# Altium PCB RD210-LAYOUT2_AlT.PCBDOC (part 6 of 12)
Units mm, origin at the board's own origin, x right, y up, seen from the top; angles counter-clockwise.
Board outline 250 x 123 mm, 4 copper layers (TOP, Mid-Layer 1, Mid-Layer 2, BOTTOM), stack 0.711 mm thick; 1043 components, 659 nets, 2786 pads, 1228 vias.
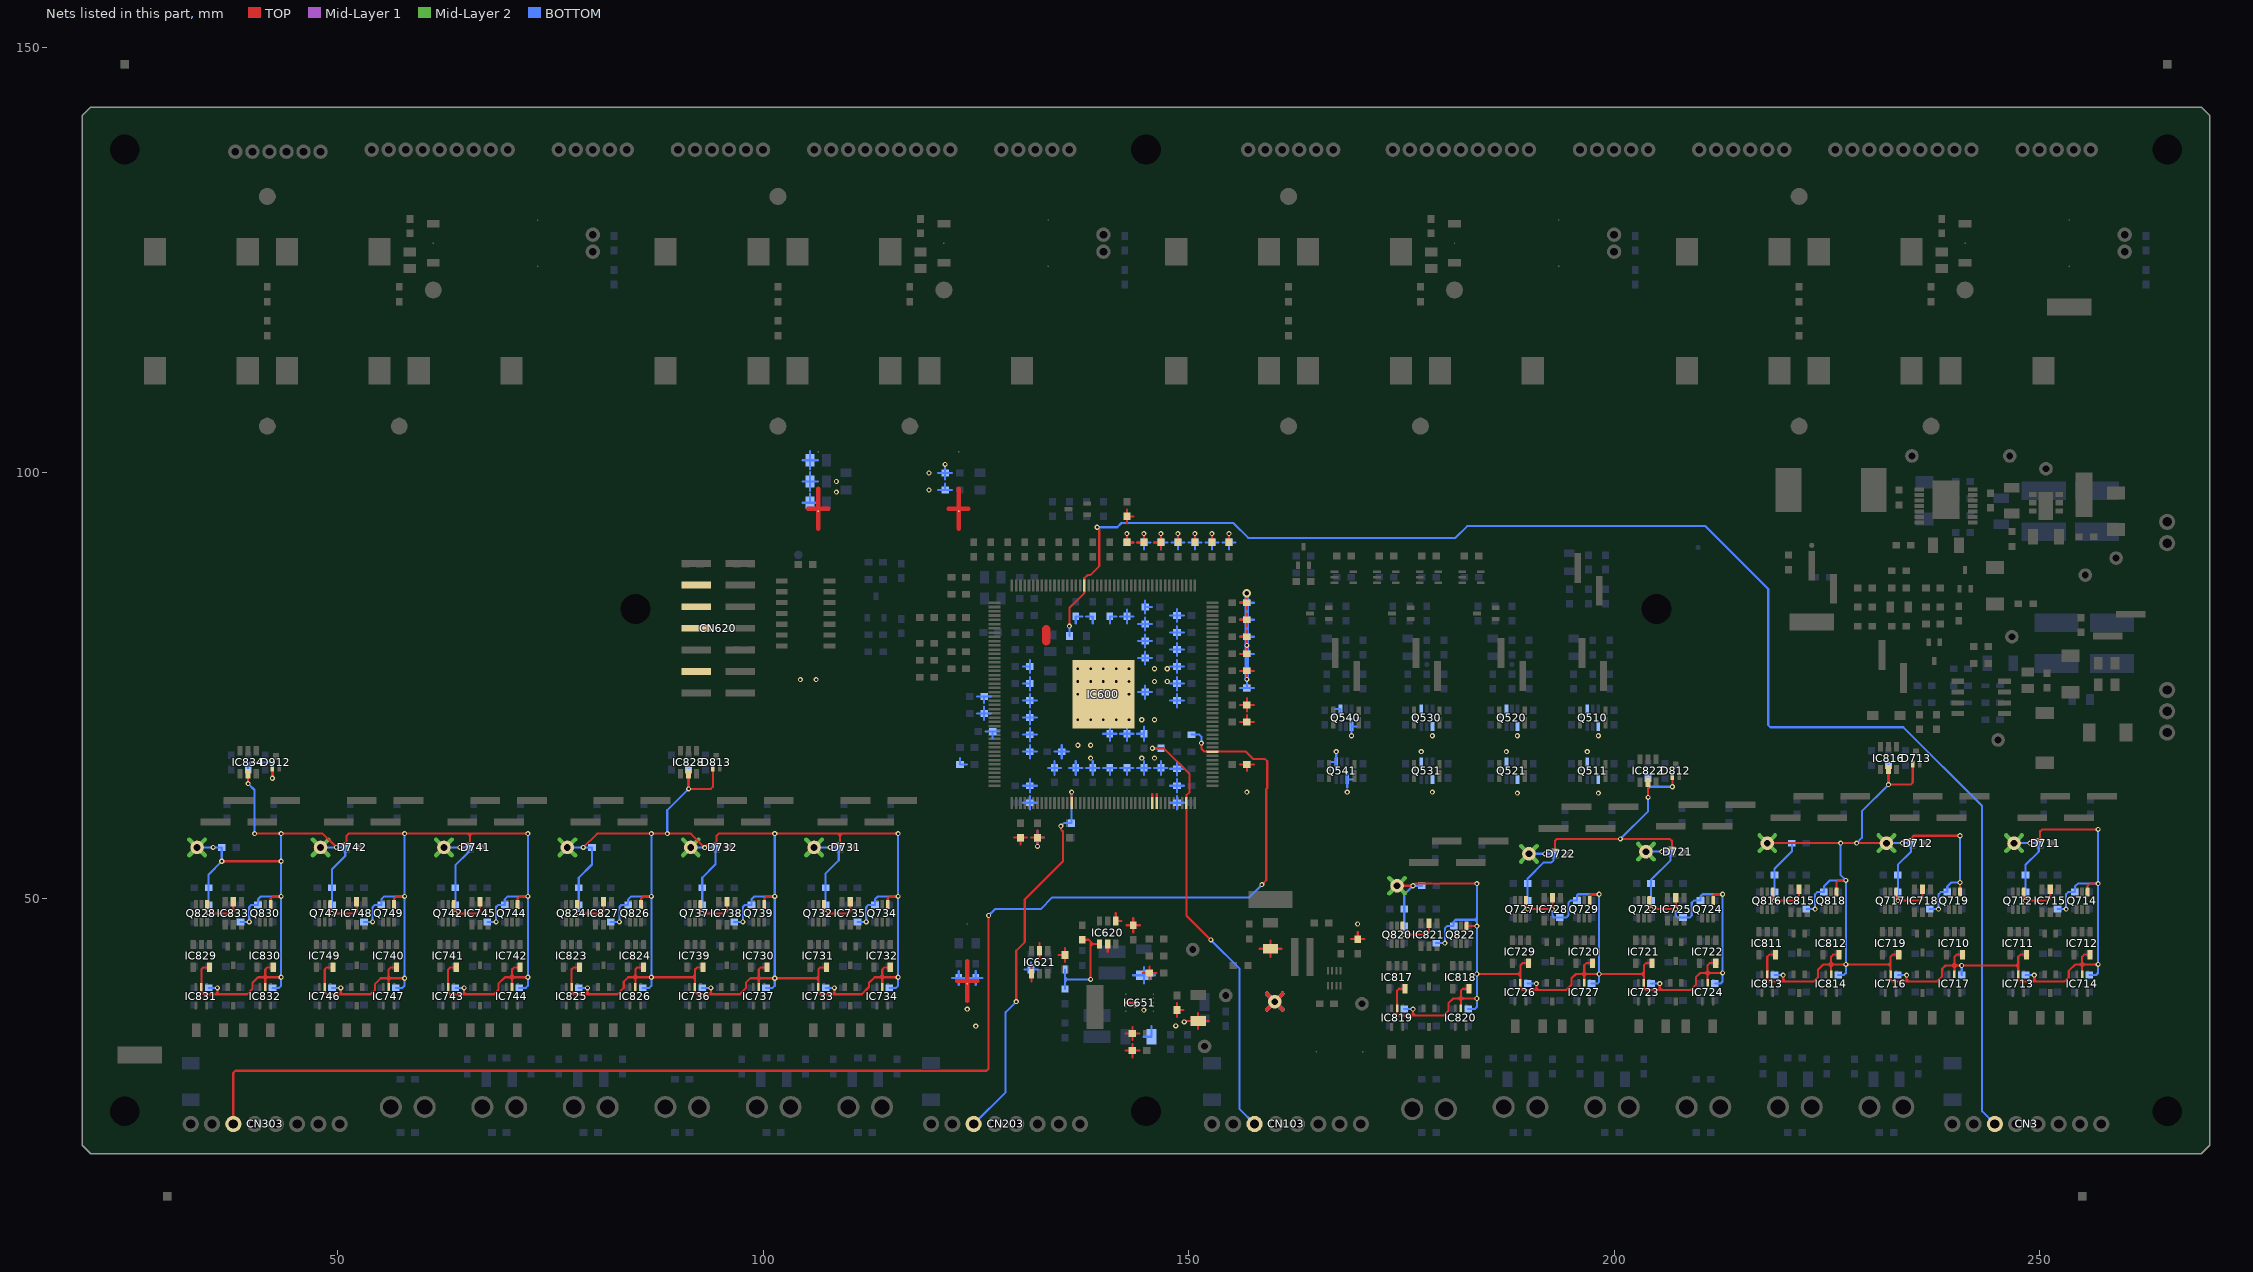
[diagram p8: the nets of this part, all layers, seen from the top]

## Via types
v1: diameter 0.6, hole 0.3, TOP to BOTTOM, 1134 vias
v2: diameter 1, hole 0.5, TOP to BOTTOM, 94 vias

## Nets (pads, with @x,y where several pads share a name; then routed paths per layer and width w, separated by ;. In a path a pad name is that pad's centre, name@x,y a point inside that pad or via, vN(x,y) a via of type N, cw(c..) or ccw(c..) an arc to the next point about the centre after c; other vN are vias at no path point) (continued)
DGND: ?.2 C620.2 C621.2 C622.1 C652.1 C654.1 C655.1 C656.1 C658.1 C659.1 C660.1 C661.1 C662.2 C663.2 C664.2 C665.1 C666.1 C667.2 C668.2 C669.2 C670.2 C671.1 C672.1 C673.1 C674.1 C675.2 C677.2 C679.2 C680.1 C681.1 C682.1 C683.1 C684.1 C685.2 C686.2 C687.2 C688.2 C689.2 C690.2 C691.2 C692.2 C693.2 C694.2 C695.1 C696.1 C697.1 C698.1 C699.1 C700.1 C701.1 C702.1 C703.1 C705.1 C716.2 C717.2 C718.2 C726.2 C727.2 C728.2 C736.2 C737.2 C738.2 C746.2 C747.2 C748.2 C756.2 C757.2 C758.2 C766.2 C767.2 C768.2 C776.2 C777.2 C778.2 C786.2 C787.2 C916.2 C917.2 C918.2 C919.2 C926.2 C927.2 C928.2 C929.2 C936.2 C937.2 C938.2 C939.2 C946.2 C947.2 C948.2 C949.2 CN502.1 CN505.1 CN512.1 CN515.1 CN620.4 CN620.8 CN620.10 CN620.12 CN912.1 CN922.1 CN925.1 CN928.1 CN931.1 CN934.1 CN938.1 CN942.1 CN958.1 D711.1 D712.1 D713.1 D721.1 D722.1 D731.1 D732.1 D741.1 D742.1 D812.1 D813.1 D912.1 IC600.122 IC600.123 IC600.177 IC620.2 IC620.4 IC621.2 IC621.4 IC651.8 IC651.11 IC710.5 IC711.5 IC712.5 IC713.2 IC714.2 IC715.2 IC716.2 IC717.2 IC718.2 IC719.5 IC720.5 IC721.5 IC722.5 IC723.2 IC724.2 IC725.2 IC726.2 IC727.2 IC728.2 IC729.5 IC730.5 IC731.5 IC732.5 IC733.2 IC734.2 IC735.2 IC736.2 IC737.2 IC738.2 IC739.5 IC740.5 IC741.5 IC742.5 IC743.2 IC744.2 IC745.2 IC746.2 IC747.2 IC748.2 IC749.5 IC811.5 IC812.5 IC813.2 IC814.2 IC815.2 IC816.2 IC817.5 IC818.5 IC819.2 IC820.2 IC821.2 IC822.2 IC823.5 IC824.5 IC825.2 IC826.2 IC827.2 IC828.2 IC829.5 IC830.5 IC831.2 IC832.2 IC833.2 IC834.2 Q510.1 Q510.4 Q511.1 Q511.4 Q520.1 Q520.4 Q521.1 Q521.4 Q530.1 Q530.4 Q531.1 Q531.4 Q540.1 Q540.4 Q541.1 Q541.4 Q712.4 Q714.4 Q717.4 Q719.4 Q722.4 Q724.4 Q727.4 Q729.4 Q732.4 Q734.4 Q737.4 Q739.4 Q742.4 Q744.4 Q747.4 Q749.4 Q816.4 Q818.4 Q820.4 Q822.4 Q824.4 Q826.4 Q828.4 Q830.4 R506.1 R507.2 R508.2 R551.1 R552.1 R553.1 R554.1 R556.1 R557.1 R558.1 R559.1 R600.1 R601.1 R602.1 R603.1 R604.1 R605.1 R606.1 R607.1 R608.1 R609.1 R613.2 R614.2 R618.2 R620.2 R623.2 R624.2 R634.1 R638.1 R639.1 R640.1 R641.1 R642.1 R643.1 R644.1 R645.1 R646.1 R647.2 R669.1 R672.1 R673.1 R677.1 R679.1 R728.1 R729.1 R734.2 R735.2 R748.1 R749.1 R754.2 R755.2 R768.1 R769.1 R774.2 R775.2 R788.1 R789.1 R794.2 R795.2 R828.1 R829.1 R834.2 R835.2 R848.1 R849.1 R854.2 R855.2 R868.1 R869.1 R874.2 R875.2 R888.1 R889.1 R894.2 R895.2 R928.1 R929.1 R934.2 R935.2 R948.1 R949.1 R954.2 R955.2 R968.1 R969.1 R974.2 R975.2 R988.1 R989.1 R994.2 R995.2 | length 1371.9
  TOP w0.25: Q828.4@34.65,49.275 34.65,48.45 v1(34.85,48.25) 37.5,48.25 37.75,48.5 IC833.2@37.75,49.6 ; IC829.5@34.95,41.9 34.25,41.9 34,41.65 IC831.2@34,39.6 34,39 34.25,38.75 35.625,38.75 ; v1(35.875,39.5) 35.875,39 ; v1(36.4,54.375) v1(43.375,54.375) ; v1(39.5,63.5) IC834.2@39.5,64.65 ; v1(40.25,57.625) v1(43.375,57.625) 48.25,57.625 v1(49.875,56) 50.275,56.4 D742.1@51.05,56.4 51.05,57.375 51.3,57.625 v1(57.875,57.625) 65.3,57.625 ; IC832.2@41.5,39.6 41.5,40.5 ; Q830.4@42.15,49.275 42.15,50 42.4,50.25 v1(43.375,50.25) ; v1(42.35,64.125) D912.1@42.35,65.3 ; IC830.5@42.45,41.9 41.75,41.9 41.5,41.65 41.5,41 ; v1(43.375,40.75) 41.75,40.75 ; Q747.4@49.15,49.275 49.15,48.45 v1(49.35,48.25) 52,48.25 52.25,48.5 IC748.2@52.25,49.6 ; IC749.5@49.45,41.9 48.75,41.9 48.5,41.65 IC746.2@48.5,39.6 48.5,39 48.75,38.75 50.125,38.75 ; v1(50.375,39.5) 50.375,39 ; IC747.2@56,39.6 56,40.375 ; Q749.4@56.65,49.275 56.65,50 56.9,50.25 v1(57.875,50.25) ; IC740.5@56.95,41.9 56.25,41.9 56,41.65 56,40.875 ; v1(57.875,40.625) 56.25,40.625 ; Q742.4@63.65,49.275 63.65,48.45 v1(63.85,48.25) 66.5,48.25 66.75,48.5 IC745.2@66.75,49.6 ; IC741.5@63.95,41.9 63.25,41.9 63,41.65 IC743.2@63,39.6 63,39 63.25,38.75 64.625,38.75 ; v1(64.375,56) 64.775,56.4 D741.1@65.55,56.4 65.55,57.375 ; v1(64.875,39.5) 64.875,39 ; IC744.2@70.5,39.6 70.5,40.5 ; Q744.4@71.15,49.275 71.15,50 71.4,50.25 v1(72.375,50.25) ; IC742.5@71.45,41.9 70.75,41.9 70.5,41.65 70.5,41 ; v1(72.375,40.75) 70.75,40.75 ; v1(72.375,57.625) 65.8,57.625 ; Q824.4@78.15,49.275 78.15,48.45 v1(78.35,48.25) 81,48.25 81.25,48.5 IC827.2@81.25,49.6 ; IC823.5@78.45,41.9 77.75,41.9 77.5,41.65 IC825.2@77.5,39.6 77.5,39 77.75,38.75 79.125,38.75 ; v1(78.875,56) 80.5,57.625 v1(86.875,57.625) v1(88.75,57.625) 91.501,57.625 v1(93.152,55.974) 93.578,56.4 D732.1@94.55,56.4 94.55,57.375 94.8,57.625 v1(101.375,57.625) 108.8,57.625 ; v1(79.375,39.5) 79.375,39 ; IC826.2@85,39.6 85,40.5 ; Q826.4@85.65,49.275 85.65,50 85.9,50.25 v1(86.875,50.25) ; IC824.5@85.95,41.9 85.25,41.9 85,41.65 85,41 ; IC828.2@91.25,64.65 v1(91.25,62.875) 93.85,62.875 94.1,63.125 D813.1@94.1,65.3 ; Q737.4@92.65,49.275 92.65,48.45 v1(92.85,48.25) 95.5,48.25 95.75,48.5 IC738.2@95.75,49.6 ; IC739.5@92.95,41.9 92.25,41.9 92,41.65 92,41 ; v1(93.875,39.5) 93.875,39 ; IC737.2@99.5,39.6 99.5,40.375 ; Q739.4@100.15,49.275 100.15,50 100.4,50.25 v1(101.375,50.25) ; IC730.5@100.45,41.9 99.75,41.9 99.5,41.65 99.5,40.875 ; Q732.4@107.15,49.275 107.15,48.45 v1(107.35,48.25) 110,48.25 110.25,48.5 IC735.2@110.25,49.6 ; IC731.5@107.45,41.9 106.75,41.9 106.5,41.65 106.5,40.875 ; v1(107.875,56) 108.275,56.4 D731.1@109.05,56.4 109.05,57.375 ; v1(108.375,39.5) 108.375,39 ; IC734.2@114,39.6 114,40.5 ; Q734.4@114.65,49.275 114.65,50 114.9,50.25 v1(115.875,50.25) ; IC732.5@114.95,41.9 114.25,41.9 114,41.65 114,41 ; v1(115.875,40.75) 114.25,40.75 ; v1(115.875,57.625) 109.3,57.625 ; 129.475,57.15 R618.2@130.25,57.15 ; 130.25,56.325 R618.2@130.25,57.15 ; 131.025,57.15 R618.2@130.25,57.15 ; 131.475,57.15 R620.2@132.25,57.15 ; 131.55,40.225 IC621.4@131.55,41.15 131.55,42.075 ; v1@132.25,56.325 R620.2@132.25,57.15 ; 132.25,57.975 R620.2@132.25,57.15 ; 132.5,42.925 IC621.2@132.5,43.85 132.5,44.775 ; 133.025,57.15 R620.2@132.25,57.15 ; 134.725,43.35 C621.2@135.5,43.35 ; 135.5,42.525 C621.2@135.5,43.35 ; 135.5,44.175 C621.2@135.5,43.35 ; 140.5,43.725 IC620.2@140.5,44.65 ; 141.45,48.275 IC620.4@141.45,47.35 142.125,47.35 ; 142.575,32.125 R672.1@143.4,32.125 ; 142.575,34.125 R679.1@143.4,34.125 ; IC651.8@142.7,37.75 143.577,37.75 ; 142.725,46.85 C620.2@143.5,46.85 ; v1@142.75,92.675 R604.1@142.75,91.85 143.525,91.85 ; 142.75,94.075 R605.1@142.75,94.9 ; 142.75,95.725 R605.1@142.75,94.9 ; 143.4,31.35 R672.1@143.4,32.125 ; 143.4,32.9 R672.1@143.4,32.125 ; 143.4,33.35 R679.1@143.4,34.125 ; 143.4,34.9 R679.1@143.4,34.125 ; 143.5,46.025 C620.2@143.5,46.85 ; 143.5,47.675 C620.2@143.5,46.85 ; 143.525,94.9 R605.1@142.75,94.9 ; 143.975,91.85 C682.1@144.75,91.85 v1@144.75,92.675 ; 144.225,32.125 R672.1@143.4,32.125 ; 144.225,34.125 R679.1@143.4,34.125 ; 144.275,46.85 C620.2@143.5,46.85 ; 144.575,41.25 R677.1@145.4,41.25 ; 145.4,40.475 R677.1@145.4,41.25 ; 145.4,42.025 R677.1@145.4,41.25 ; 145.975,91.85 R609.1@146.75,91.85 ; 146.225,41.25 R677.1@145.4,41.25 ; 146.75,91.025 R609.1@146.75,91.85 ; v1@146.75,92.675 R609.1@146.75,91.85 ; 148.625,36.075 C702.1@148.625,36.9 ; 148.625,37.725 C702.1@148.625,36.9 ; R607.1@148.75,91.85 v1@148.75,92.675 ; 149.4,36.9 C702.1@148.625,36.9 ; 149.85,35.6 C701.1@151.125,35.6 ; R559.1@150.75,91.85 v1@150.75,92.675 ; 151.125,34.65 C701.1@151.125,35.6 ; 151.125,36.55 C701.1@151.125,35.6 ; 152.4,35.6 C701.1@151.125,35.6 ; C680.1@152.75,91.85 v1@152.75,92.675 ; R553.1@154.75,91.85 v1@154.75,92.675 ; 156.025,65.75 C696.1@156.85,65.75 ; 156.025,70.75 C697.1@156.85,70.75 ; 156.025,72.75 C698.1@156.85,72.75 ; 156.025,76.75 R551.1@156.85,76.75 ; 156.025,78.75 R552.1@156.85,78.75 v1@156.85,79.525 ; 156.025,80.75 C700.1@156.85,80.75 ; 156.025,82.75 R642.1@156.85,82.75 ; 156.025,84.75 R645.1@156.85,84.75 ; 156.85,64.975 C696.1@156.85,65.75 ; 156.85,71.525 C697.1@156.85,70.75 ; 156.85,71.975 C698.1@156.85,72.75 ; 156.85,73.525 C698.1@156.85,72.75 ; v1@156.85,75.975 R551.1@156.85,76.75 ; v1@156.85,79.975 C700.1@156.85,80.75 ; 156.85,81.525 C700.1@156.85,80.75 ; 156.85,81.975 R642.1@156.85,82.75 ; 156.85,83.525 R642.1@156.85,82.75 ; 156.85,83.975 R645.1@156.85,84.75 ; v2@156.85,85.525 R645.1@156.85,84.75 ; 157.675,65.75 C696.1@156.85,65.75 ; 157.675,70.75 C697.1@156.85,70.75 ; 157.675,72.75 C698.1@156.85,72.75 ; 157.675,76.75 R551.1@156.85,76.75 ; 158.35,44.1 C652.1@159.625,44.1 ; 159.625,43.15 C652.1@159.625,44.1 ; 159.625,45.05 C652.1@159.625,44.1 ; 160.9,44.1 C652.1@159.625,44.1 ; 169.1,45.225 R673.1@169.875,45.225 ; 169.875,46.05 R673.1@169.875,45.225 ; 170.65,45.225 R673.1@169.875,45.225 ; CN922.1@174.5,51.5 v1(176.375,51.5) 176.625,51.75 v1(183.875,51.75) ; Q820.4@175.15,46.775 175.15,45.95 v1(175.35,45.75) 178,45.75 178.25,46 IC821.2@178.25,47.1 ; IC817.5@175.45,39.4 174.75,39.4 174.5,39.15 IC819.2@174.5,37.1 174.5,36.5 174.75,36.25 176.125,36.25 ; v1(176.375,37) 176.375,36.5 ; IC820.2@182,37.1 182,38 ; Q822.4@182.65,46.775 183.85,46.775 v1(183.875,46.75) ; IC818.5@182.95,39.4 182.25,39.4 182,39.15 182,38.5 ; v1(183.875,38.25) 182.25,38.25 ; v1(183.875,41.125) 188.75,41.125 ; Q727.4@189.65,49.775 189.65,48.95 v1(189.85,48.75) v1(192.75,48.75) IC728.2@192.75,50.1 ; IC729.5@189.95,42.4 189.25,42.4 189,42.15 189,41.375 ; v1(190.875,40) 190.875,39.5 ; v1(191.875,55.25) 192.275,55.65 D722.1@193.05,55.65 193.05,56.75 193.3,57 v1(200.75,57) 206.55,57 206.8,56.75 D721.1@206.8,55.9 206.025,55.9 v1(205.625,55.5) ; IC727.2@196.5,40.1 196.5,40.875 ; Q729.4@197.15,49.775 197.15,50.4 197.25,50.5 v1(198.25,50.5) ; IC720.5@197.45,42.4 196.75,42.4 196.5,42.15 196.5,41.375 ; v1(204,61.875) IC822.2@204,63.65 ; Q722.4@204.15,49.775 204.15,48.95 v1(204.35,48.75) v1(207.25,48.75) IC725.2@207.25,50.1 ; IC721.5@204.45,42.4 203.75,42.4 203.5,42.15 203.5,41.375 ; v1(205.375,40) 205.375,39.5 ; v1(206.85,63.125) D812.1@206.85,64.3 ; IC724.2@211,40.1 211,41 ; Q724.4@211.65,49.775 211.65,50.4 211.75,50.5 v1(212.75,50.5) ; IC722.5@211.95,42.4 211.25,42.4 211,42.15 211,41.5 ; v1(212.75,41.25) 211.25,41.25 ; CN912.1@218,56.5 v1(226.625,56.5) v1(228.5,56.5) CN505.1@232,56.5 ; Q816.4@218.65,50.775 218.65,49.95 v1(218.85,49.75) 221.5,49.75 221.75,50 IC815.2@221.75,51.1 ; IC811.5@218.95,43.4 218.25,43.4 218,43.15 IC813.2@218,41.1 218,40.5 218.25,40.25 219.625,40.25 ; v1(219.875,41) 219.875,40.5 ; IC814.2@225.5,41.1 225.5,42 ; Q818.4@226.15,50.775 226.15,51.9 226.375,52.125 v1(227.25,52.125) ; IC812.5@226.45,43.4 225.75,43.4 225.5,43.15 225.5,42.5 ; IC816.2@232.25,65.15 v1(232.25,63.375) 234.85,63.375 235.1,63.625 D713.1@235.1,65.8 ; Q717.4@233.15,50.775 233.15,49.95 v1(233.35,49.75) 236,49.75 236.25,50 IC718.2@236.25,51.1 ; IC719.5@233.45,43.4 232.75,43.4 232.5,43.15 232.5,42.5 ; v1(233.875,56.5) 234.275,56.9 D712.1@235.05,56.9 235.05,57.25 235.175,57.375 v1(240.65,57.375) ; v1(234.375,41) 234.375,40.5 ; IC717.2@240,41.1 240,41.875 ; Q719.4@240.65,50.775 v1(240.65,51.875) ; IC710.5@240.95,43.4 240.25,43.4 240,43.15 240,42.375 ; Q712.4@248.15,50.775 248.15,49.95 v1(248.35,49.75) 251,49.75 251.25,50 IC715.2@251.25,51.1 ; IC711.5@248.45,43.4 247.75,43.4 247.5,43.15 247.5,42.375 ; v1(248.875,56.5) 249.275,56.9 D711.1@250.05,56.9 250.05,57.875 250.3,58.125 v1(256.875,58.125) ; v1(249.375,41) 249.375,40.5 ; IC714.2@255,41.1 255,42 ; Q714.4@255.65,50.775 255.65,51.5 255.9,51.75 v1(256.875,51.75) ; IC712.5@255.95,43.4 255.25,43.4 255,43.15 255,42.5 ; v1(256.875,42.25) 255.25,42.25 ; 35.625,38.75 35.875,39 ; 35.625,38.75 36.125,38.75 ; 35.875,39 36.125,38.75 ; 36.125,38.75 39.375,38.75 40.003,39.377 40.003,40.099 40.653,40.75 41.25,40.75 ; 41.25,40.75 41.5,41 ; 41.25,40.75 41.75,40.75 ; 41.25,40.75 41.5,40.5 ; 41.5,40.5 41.75,40.75 ; 41.5,41 41.75,40.75 ; 50.125,38.75 50.375,39 ; 50.125,38.75 50.625,38.75 ; 50.375,39 50.625,38.75 ; 50.625,38.75 53.875,38.75 54.417,39.292 54.417,39.972 55.07,40.625 55.75,40.625 ; 55.75,40.625 56,40.875 ; 55.75,40.625 56,40.375 ; 55.75,40.625 56.25,40.625 ; 56,40.375 56.25,40.625 ; 56,40.875 56.25,40.625 ; 64.625,38.75 64.875,39 ; 64.625,38.75 65.125,38.75 ; 64.875,39 65.125,38.75 ; 65.125,38.75 68.375,38.75 68.895,39.27 68.895,39.972 69.673,40.75 70.25,40.75 ; 65.3,57.625 65.55,57.375 ; 65.3,57.625 65.8,57.625 ; 65.55,57.375 65.8,57.625 ; 70.25,40.75 70.5,41 ; 70.25,40.75 70.75,40.75 ; 70.25,40.75 70.5,40.5 ; 70.5,40.5 70.75,40.75 ; 70.5,41 70.75,40.75 ; 79.125,38.75 79.375,39 ; 79.125,38.75 79.625,38.75 ; 79.375,39 79.625,38.75 ; 79.625,38.75 82.875,38.75 83.627,39.502 83.627,40.226 84.151,40.75 84.75,40.75 ; 84.75,40.75 85,41 ; 84.75,40.75 85.25,40.75 ; 84.75,40.75 85,40.5 ; 85,40.5 85.25,40.75 ; 85,41 85.25,40.75 ; 85.25,40.75 v1(86.875,40.75) 91.75,40.75 ; 91.75,40.75 92,40.5 ; 91.75,40.75 92,41 ; 92,40.5 IC736.2@92,39.6 92,39 92.25,38.75 93.625,38.75 ; 92,40.5 92,41 ; 93.625,38.75 93.875,39 ; 93.625,38.75 94.125,38.75 ; 93.875,39 94.125,38.75 ; 94.125,38.75 97.264,38.75 97.978,39.464 97.978,40.099 98.504,40.625 99.25,40.625 ; 99.25,40.625 99.5,40.375 ; 99.25,40.625 99.75,40.625 ; 99.25,40.625 99.5,40.875 ; 99.5,40.375 99.75,40.625 ; 99.5,40.875 99.75,40.625 ; 99.75,40.625 v1(101.375,40.625) 106.25,40.625 ; 106.25,40.625 106.5,40.875 ; 106.25,40.625 106.5,40.375 ; 106.5,40.375 106.5,40.875 ; 106.5,40.375 IC733.2@106.5,39.6 106.5,39 106.75,38.75 108.125,38.75 ; 108.125,38.75 108.375,39 ; 108.125,38.75 108.625,38.75 ; 108.375,39 108.625,38.75 ; 108.625,38.75 111.615,38.75 112.456,39.591 112.456,40.099 113.107,40.75 113.75,40.75 ; 108.8,57.625 109.05,57.375 ; 108.8,57.625 109.3,57.625 ; 109.05,57.375 109.3,57.625 ; 113.75,40.75 114,41 ; 113.75,40.75 114.25,40.75 ; 113.75,40.75 114,40.5 ; 114,40.5 114.25,40.75 ; 114,41 114.25,40.75 ; 176.125,36.25 176.625,36.25 ; 176.125,36.25 176.375,36.5 ; 176.375,36.5 176.625,36.25 ; 176.625,36.25 179.981,36.25 180.528,36.797 180.528,37.686 181.092,38.25 181.75,38.25 ; 181.75,38.25 182,38.5 ; 181.75,38.25 182.25,38.25 ; 181.75,38.25 182,38 ; 182,38 182.25,38.25 ; 182,38.5 182.25,38.25 ; 188.75,41.125 189,40.875 ; 188.75,41.125 189,41.375 ; 189,40.875 IC726.2@189,40.1 189,39.5 189.25,39.25 190.625,39.25 ; 189,40.875 189,41.375 ; 190.625,39.25 190.875,39.5 ; 190.625,39.25 191.125,39.25 ; 190.875,39.5 191.125,39.25 ; 191.125,39.25 194.375,39.25 195.006,39.881 195.006,40.607 195.524,41.125 196.25,41.125 ; 196.25,41.125 196.5,41.375 ; 196.25,41.125 196.75,41.125 ; 196.25,41.125 196.5,40.875 ; 196.5,40.875 196.75,41.125 ; 196.5,41.375 196.75,41.125 ; 196.75,41.125 v1(198.25,41.125) 203.25,41.125 ; 203.25,41.125 203.5,40.875 ; 203.25,41.125 203.5,41.375 ; 203.5,40.875 IC723.2@203.5,40.1 203.5,39.5 203.75,39.25 205.125,39.25 ; 203.5,40.875 203.5,41.375 ; 205.125,39.25 205.375,39.5 ; 205.125,39.25 205.625,39.25 ; 205.375,39.5 205.625,39.25 ; 205.625,39.25 209.016,39.25 209.611,39.845 209.611,40.734 210.127,41.25 210.75,41.25 ; 210.75,41.25 211,41 ; 210.75,41.25 211.25,41.25 ; 210.75,41.25 211,41.5 ; 211,41 211.25,41.25 ; 211,41.5 211.25,41.25 ; 219.625,40.25 220.125,40.25 ; 219.625,40.25 219.875,40.5 ; 219.875,40.5 220.125,40.25 ; 220.125,40.25 223.478,40.25 223.962,40.734 223.962,41.623 224.589,42.25 225.25,42.25 ; 225.25,42.25 225.75,42.25 ; 225.25,42.25 225.5,42 ; 225.25,42.25 225.5,42.5 ; 225.5,42 225.75,42.25 ; 225.5,42.5 225.75,42.25 ; 225.75,42.25 v1(227.25,42.25) 232.25,42.25 ; 232.25,42.25 232.5,42.5 ; 232.25,42.25 232.5,42 ; 232.5,42 IC716.2@232.5,41.1 232.5,40.5 232.75,40.25 234.125,40.25 ; 232.5,42 232.5,42.5 ; 234.125,40.25 234.375,40.5 ; 234.125,40.25 234.625,40.25 ; 234.375,40.5 234.625,40.25 ; 234.625,40.25 237.956,40.25 238.567,40.861 238.567,41.75 238.942,42.125 239.75,42.125 ; 239.75,42.125 240,41.875 ; 239.75,42.125 240.25,42.125 ; 239.75,42.125 240,42.375 ; 240,41.875 240.25,42.125 ; 240,42.375 240.25,42.125 ; 240.25,42.125 v1(240.85,42.125) 247.25,42.125 ; 247.25,42.125 247.5,42.375 ; 247.25,42.125 247.5,41.875 ; 247.5,41.875 247.5,42.375 ; 247.5,41.875 IC713.2@247.5,41.1 247.5,40.5 247.75,40.25 249.125,40.25 ; 249.125,40.25 249.375,40.5 ; 249.125,40.25 249.625,40.25 ; 249.375,40.5 249.625,40.25 ; 249.625,40.25 252.942,40.25 253.426,40.734 253.426,41.496 254.18,42.25 254.75,42.25 ; 254.75,42.25 255,42.5 ; 254.75,42.25 255.25,42.25 ; 254.75,42.25 255,42 ; 255,42 255.25,42.25 ; 255,42.5 255.25,42.25
  TOP w0.3: IC600.122@145.75,61.2 145.75,62.25 ; IC600.123@146.25,61.2 146.25,62.25
  TOP w0.5: 105.296,95.8 106.5,95.8 ; 106.5,93.446 C664.2@106.5,95.5 106.5,95.8 ; 106.5,98.154 106.5,95.8 ; 107.704,95.8 106.5,95.8 ; 121.796,95.8 123,95.8 ; 122.796,40.3 124,40.3 ; 123,93.446 C663.2@123,95.5 123,95.8 ; 123,98.154 123,95.8 ; 124,37.946 C662.2@124,40 124,40.3 ; 124,42.654 124,40.3 ; 124.125,95.8 123,95.8 ; 125.204,40.3 124,40.3 ; 159.206,36.956 CN958.1@160.125,37.875 ; 159.206,38.794 CN958.1@160.125,37.875 ; 161.044,36.956 CN958.1@160.125,37.875 ; 161.044,38.794 CN958.1@160.125,37.875
  TOP w1: 133.25,80.25 133.25,81.625
  Mid-Layer 1 w0.5: 159.206,36.956 CN958.1@160.125,37.875 ; 159.206,38.794 CN958.1@160.125,37.875 ; 161.044,36.956 CN958.1@160.125,37.875 ; 161.044,38.794 CN958.1@160.125,37.875
  Mid-Layer 2 w0.5: 32.581,55.081 CN942.1@33.5,56 ; 32.581,56.919 CN942.1@33.5,56 ; 34.419,55.081 CN942.1@33.5,56 ; 34.419,56.919 CN942.1@33.5,56 ; 47.081,55.081 CN934.1@48,56 ; 47.081,56.919 CN934.1@48,56 ; 48.919,55.081 CN934.1@48,56 ; 48.919,56.919 CN934.1@48,56 ; 61.581,55.081 CN931.1@62.5,56 ; 61.581,56.919 CN931.1@62.5,56 ; 63.419,55.081 CN931.1@62.5,56 ; 63.419,56.919 CN931.1@62.5,56 ; 76.081,55.081 CN938.1@77,56 ; 76.081,56.919 CN938.1@77,56 ; 77.919,55.081 CN938.1@77,56 ; 77.919,56.919 CN938.1@77,56 ; 90.581,55.081 CN928.1@91.5,56 ; 90.581,56.919 CN928.1@91.5,56 ; 92.419,55.081 CN928.1@91.5,56 ; 92.419,56.919 CN928.1@91.5,56 ; 105.081,55.081 CN925.1@106,56 ; 105.081,56.919 CN925.1@106,56 ; 106.919,55.081 CN925.1@106,56 ; 106.919,56.919 CN925.1@106,56 ; 159.206,36.956 CN958.1@160.125,37.875 ; 159.206,38.794 CN958.1@160.125,37.875 ; 161.044,36.956 CN958.1@160.125,37.875 ; 161.044,38.794 CN958.1@160.125,37.875 ; 173.581,50.581 CN922.1@174.5,51.5 ; 173.581,52.419 CN922.1@174.5,51.5 ; 175.419,50.581 CN922.1@174.5,51.5 ; 175.419,52.419 CN922.1@174.5,51.5 ; 189.081,54.331 CN515.1@190,55.25 ; 189.081,56.169 CN515.1@190,55.25 ; 190.919,54.331 CN515.1@190,55.25 ; 190.919,56.169 CN515.1@190,55.25 ; 202.831,54.581 CN512.1@203.75,55.5 ; 202.831,56.419 CN512.1@203.75,55.5 ; 204.669,54.581 CN512.1@203.75,55.5 ; 204.669,56.419 CN512.1@203.75,55.5 ; 217.081,55.581 CN912.1@218,56.5 ; 217.081,57.419 CN912.1@218,56.5 ; 218.919,55.581 CN912.1@218,56.5 ; 218.919,57.419 CN912.1@218,56.5 ; 231.081,55.581 CN505.1@232,56.5 ; 231.081,57.419 CN505.1@232,56.5 ; 232.919,55.581 CN505.1@232,56.5 ; 232.919,57.419 CN505.1@232,56.5 ; 246.081,55.581 CN502.1@247,56.5 ; 246.081,57.419 CN502.1@247,56.5 ; 247.919,55.581 CN502.1@247,56.5 ; 247.919,57.419 CN502.1@247,56.5
  BOTTOM w0.25: CN942.1@33.5,56 v1(35.375,56) C948.2@36.4,56 v1(36.4,54.375) 34.85,52.825 R994.2@34.85,51.25 R988.1@34.85,49.25 v1(34.85,48.25) ; C946.2@34.85,39.5 v1(35.875,39.5) ; R989.1@38.6,47.25 v1(39.625,47.25) 39.625,49 39.875,49.25 R995.2@40.65,49.25 40.65,49.9 41,50.25 v1(43.375,50.25) ; v1(40.25,57.625) 40.25,62.75 v1(39.5,63.5) C949.2@39.5,65.15 39.5,65.75 39.75,66 42.1,66 42.35,65.75 v1(42.35,64.125) ; C947.2@42.35,39.5 43.125,39.5 43.375,39.75 v1(43.375,40.75) v1(43.375,50.25) ; v1(43.375,57.625) v1(43.375,54.375) v1(43.375,50.25) ; CN934.1@48,56 v1(49.875,56) ?.2@50.9,56 50.9,55 49.35,53.45 R894.2@49.35,51.25 R888.1@49.35,49.25 v1(49.35,48.25) ; C786.2@49.35,39.5 v1(50.375,39.5) ; R889.1@53.1,47.25 v1(54.125,47.25) 54.125,49 54.375,49.25 R895.2@55.15,49.25 55.15,49.9 55.5,50.25 v1(57.875,50.25) ; C787.2@56.85,39.5 57.625,39.5 57.875,39.75 v1(57.875,40.625) v1(57.875,50.25) ; v1(57.875,57.625) v1(57.875,50.25) ; CN931.1@62.5,56 v1(64.375,56) C778.2@65.4,56 65.4,55.464 63.85,53.913 R794.2@63.85,51.25 R788.1@63.85,49.25 v1(63.85,48.25) ; C776.2@63.85,39.5 v1(64.875,39.5) ; R789.1@67.6,47.25 v1(68.625,47.25) 68.625,49 68.875,49.25 R795.2@69.65,49.25 69.65,49.9 70,50.25 v1(72.375,50.25) ; C777.2@71.35,39.5 72.125,39.5 72.375,39.75 v1(72.375,40.75) v1(72.375,50.25) ; v1(72.375,57.625) v1(72.375,50.25) ; CN938.1@77,56 v1(78.875,56) C938.2@79.9,56 79.9,54 78.35,52.45 R974.2@78.35,51.25 R968.1@78.35,49.25 v1(78.35,48.25) ; C936.2@78.35,39.5 v1(79.375,39.5) ; R969.1@82.1,47.25 v1(83.125,47.25) 83.125,49 83.375,49.25 R975.2@84.15,49.25 84.15,49.9 84.5,50.25 v1(86.875,50.25) ; C937.2@85.85,39.5 86.625,39.5 86.875,39.75 v1(86.875,40.75) v1(86.875,50.25) ; v1(86.875,57.625) v1(86.875,50.25) ; v1(88.75,57.625) 88.75,60.375 v1(91.25,62.875) C939.2@91.25,65.15 ; CN928.1@91.5,56 C768.2@94.4,56 94.4,54 92.85,52.45 R874.2@92.85,51.25 R868.1@92.85,49.25 v1(92.85,48.25) ; C766.2@92.85,39.5 v1(93.875,39.5) ; R869.1@96.6,47.25 v1(97.625,47.25) 97.625,49 97.875,49.25 R875.2@98.65,49.25 98.65,49.9 99,50.25 v1(101.375,50.25) ; C767.2@100.35,39.5 101.125,39.5 101.375,39.75 v1(101.375,40.625) v1(101.375,50.25) ; v1(101.375,57.625) v1(101.375,50.25) ; 104.625,96.5 C654.1@105.525,96.5 ; 104.625,99 C661.1@105.525,99 ; 104.625,101.5 C658.1@105.525,101.5 ; 105.525,97.6 C654.1@105.525,96.5 ; 105.525,97.9 C661.1@105.525,99 ; 105.525,100.1 C661.1@105.525,99 ; 105.525,100.4 C658.1@105.525,101.5 ; 105.525,102.6 C658.1@105.525,101.5 ; CN925.1@106,56 v1(107.875,56) C758.2@108.9,56 108.9,54.5 107.35,52.95 R774.2@107.35,51.25 R768.1@107.35,49.25 v1(107.35,48.25) ; 106.425,96.5 C654.1@105.525,96.5 ; 106.425,99 C661.1@105.525,99 ; 106.425,101.5 C658.1@105.525,101.5 ; C756.2@107.35,39.5 v1(108.375,39.5) ; R769.1@111.1,47.25 v1(112.125,47.25) 112.125,49 112.375,49.25 R775.2@113.15,49.25 113.15,49.9 113.5,50.25 v1(115.875,50.25) ; C757.2@114.85,39.5 115.625,39.5 115.875,39.75 v1(115.875,40.75) v1(115.875,50.25) ; v1(115.875,57.625) v1(115.875,50.25) ; 120.575,98 C656.1@121.4,98 ; 120.575,100 C660.1@121.4,100 ; 121.4,98.775 C656.1@121.4,98 ; 121.4,99.225 C660.1@121.4,100 ; v1@121.4,100.775 C660.1@121.4,100 ; 122.225,40.65 C655.1@123,40.65 ; 122.225,98 C656.1@121.4,98 ; 122.225,100 C660.1@121.4,100 ; 123,39.825 C655.1@123,40.65 ; 123,41.475 C655.1@123,40.65 ; 123.15,66.525 R669.1@123.15,65.75 123.975,65.75 ; 123.775,40.65 C655.1@123,40.65 ; 124.225,40.65 C659.1@125,40.65 ; 125,39.825 C659.1@125,40.65 ; 125,41.475 C659.1@125,40.65 ; 125.15,71.75 C675.2@125.975,71.75 ; 125.15,73.75 R613.2@125.975,73.75 ; 125.775,40.65 C659.1@125,40.65 ; 125.975,70.975 C675.2@125.975,71.75 ; 125.975,72.525 C675.2@125.975,71.75 ; 125.975,72.975 R613.2@125.975,73.75 ; 126.15,69.625 C687.2@126.975,69.625 ; 126.8,71.75 C675.2@125.975,71.75 ; 126.8,73.75 R613.2@125.975,73.75 ; 126.975,68.85 C687.2@126.975,69.625 ; 127.8,69.625 C687.2@126.975,69.625 ; 130.525,61.25 C690.2@131.35,61.25 ; 130.525,63.25 C689.2@131.35,63.25 ; 130.525,67.25 C688.2@131.35,67.25 ; 130.525,69.25 C668.2@131.35,69.25 ; 130.525,71.25 R614.2@131.35,71.25 ; 130.525,73.25 C686.2@131.35,73.25 ; 130.525,75.25 C685.2@131.35,75.25 ; 130.525,77.25 C667.2@131.35,77.25 ; 130.725,41.65 C622.1@131.5,41.65 ; 131.35,60.475 C690.2@131.35,61.25 ; 131.35,62.025 C690.2@131.35,61.25 ; 131.35,62.475 C689.2@131.35,63.25 ; 131.35,64.025 C689.2@131.35,63.25 ; 131.35,66.475 C688.2@131.35,67.25 ; 131.35,68.025 C688.2@131.35,67.25 ; 131.35,68.475 C668.2@131.35,69.25 ; 131.35,70.025 C668.2@131.35,69.25 ; 131.35,70.475 R614.2@131.35,71.25 ; 131.35,72.025 R614.2@131.35,71.25 ; 131.35,72.475 C686.2@131.35,73.25 ; 131.35,74.025 C686.2@131.35,73.25 ; 131.35,74.475 C685.2@131.35,75.25 ; 131.35,76.025 C685.2@131.35,75.25 ; 131.35,76.475 C667.2@131.35,77.25 ; 131.35,78.025 C667.2@131.35,77.25 ; 131.5,40.825 C622.1@131.5,41.65 ; 131.5,42.475 C622.1@131.5,41.65 ; 132.175,61.25 C690.2@131.35,61.25 ; 132.175,63.25 C689.2@131.35,63.25 ; 132.175,67.25 C688.2@131.35,67.25 ; 132.175,69.25 C668.2@131.35,69.25 ; 132.175,71.25 R614.2@131.35,71.25 ; 132.175,73.25 C686.2@131.35,73.25 ; v1@132.25,56.325 R508.2@132.25,57.15 ; 132.25,57.975 R508.2@132.25,57.15 ; 132.275,41.65 C622.1@131.5,41.65 ; 133.025,57.15 R508.2@132.25,57.15 ; 133.475,65.35 C691.2@134.25,65.35 ; 134.25,64.525 C691.2@134.25,65.35 ; 134.25,66.175 C691.2@134.25,65.35 ; 134.275,67.25 R507.2@135.1,67.25 ; 135.025,65.35 C691.2@134.25,65.35 ; 135.1,66.475 R507.2@135.1,67.25 ; 135.1,68.025 R507.2@135.1,67.25 ; 135.925,67.25 R507.2@135.1,67.25 ; 135.975,65.35 C692.2@136.75,65.35 ; 136.75,64.525 C692.2@136.75,65.35 ; 136.75,66.175 C692.2@136.75,65.35 ; 136.75,82.325 C684.1@136.75,83.15 137.525,83.15 ; 137.525,65.35 C692.2@136.75,65.35 ; 137.975,65.35 C693.2@138.75,65.35 ; 137.975,83.15 C666.1@138.75,83.15 138.75,82.325 ; 138.75,64.525 C693.2@138.75,65.35 ; 138.75,66.175 C693.2@138.75,65.35 ; 139.525,65.35 C693.2@138.75,65.35 ; 139.975,65.35 C694.2@140.75,65.35 ; 139.975,69.35 R623.2@140.75,69.35 ; 140.75,64.525 C694.2@140.75,65.35 ; 140.75,68.525 R623.2@140.75,69.35 ; 140.75,70.175 R623.2@140.75,69.35 ; 140.75,82.325 C683.1@140.75,83.15 141.525,83.15 ; 141.525,65.35 C694.2@140.75,65.35 ; 141.525,69.35 R623.2@140.75,69.35 ; 141.975,65.35 C669.2@142.75,65.35 ; 141.975,69.35 R647.2@142.75,69.35 ; 141.975,83.15 C665.1@142.75,83.15 ; 142.75,64.525 C669.2@142.75,65.35 ; 142.75,68.525 R647.2@142.75,69.35 ; 142.75,70.175 R647.2@142.75,69.35 ; 142.75,82.325 C665.1@142.75,83.15 ; 142.75,83.975 C665.1@142.75,83.15 ; v1@142.75,92.675 R646.1@142.75,91.85 143.525,91.85 ; 143.475,40.975 C705.1@144.75,40.975 ; 143.525,65.35 C669.2@142.75,65.35 ; 143.525,69.35 R647.2@142.75,69.35 ; 143.525,83.15 C665.1@142.75,83.15 ; 143.975,65.35 C677.2@144.75,65.35 ; 143.975,69.35 R624.2@144.75,69.35 ; 143.975,91.85 R506.1@144.75,91.85 ; 144.075,74.25 R639.1@144.9,74.25 ; 144.075,78.25 R601.1@144.9,78.25 ; 144.075,80.25 R603.1@144.9,80.25 ; 144.075,82.25 R641.1@144.9,82.25 ; 144.7,33.75 C703.1@145.65,33.75 145.65,35.025 ; 144.75,40.025 C705.1@144.75,40.975 ; 144.75,41.925 C705.1@144.75,40.975 ; 144.75,64.525 C677.2@144.75,65.35 ; 144.75,66.175 C677.2@144.75,65.35 ; 144.75,68.525 R624.2@144.75,69.35 ; 144.75,70.175 R624.2@144.75,69.35 ; 144.75,91.025 R506.1@144.75,91.85 ; v1@144.75,92.675 R506.1@144.75,91.85 ; 144.9,73.475 R639.1@144.9,74.25 ; 144.9,75.025 R639.1@144.9,74.25 ; 144.9,77.475 R601.1@144.9,78.25 ; 144.9,79.025 R601.1@144.9,78.25 ; 144.9,79.475 R603.1@144.9,80.25 ; 144.9,81.025 R603.1@144.9,80.25 ; 144.9,81.475 R641.1@144.9,82.25 ; 144.9,83.025 R641.1@144.9,82.25 ; 144.9,83.475 R634.1@144.9,84.25 ; 144.9,85.025 R634.1@144.9,84.25 ; 145.525,65.35 C677.2@144.75,65.35 ; 145.525,91.85 R506.1@144.75,91.85 ; 145.725,74.25 R639.1@144.9,74.25 ; 145.725,78.25 R601.1@144.9,78.25 ; 145.725,80.25 R603.1@144.9,80.25 ; 145.725,82.25 R641.1@144.9,82.25 ; 145.725,84.25 R634.1@144.9,84.25 ; 145.975,65.35 C679.2@146.75,65.35 ; 145.975,91.85 C681.1@146.75,91.85 ; 146.025,40.975 C705.1@144.75,40.975 ; 146.75,64.525 C679.2@146.75,65.35 ; 146.75,66.175 C679.2@146.75,65.35 ; 146.75,91.025 C681.1@146.75,91.85 ; v1@146.75,92.675 C681.1@146.75,91.85 ; 147.525,65.35 C679.2@146.75,65.35 ; 147.525,91.85 C681.1@146.75,91.85 ; 147.825,61.25 C695.1@148.65,61.25 ; 147.825,63.25 C670.2@148.65,63.25 ; 147.825,65.25 C671.1@148.65,65.25 ; 147.825,73.25 C672.1@148.65,73.25 ; 147.825,75.25 C699.1@148.65,75.25 ; 147.825,77.25 R556.1@148.65,77.25 ; 147.825,79.25 R557.1@148.65,79.25 ; 147.825,81.25 C674.1@148.65,81.25 ; 147.825,83.25 R643.1@148.65,83.25 ; 147.975,91.85 R608.1@148.75,91.85 ; 148.65,60.475 C695.1@148.65,61.25 ; 148.65,62.025 C695.1@148.65,61.25 ; 148.65,62.475 C670.2@148.65,63.25 ; 148.65,64.025 C670.2@148.65,63.25 ; 148.65,64.475 C671.1@148.65,65.25 ; 148.65,66.025 C671.1@148.65,65.25 ; 148.65,72.475 C672.1@148.65,73.25 ; 148.65,74.025 C672.1@148.65,73.25 ; 148.65,74.475 C699.1@148.65,75.25 ; 148.65,76.025 C699.1@148.65,75.25 ; 148.65,76.475 R556.1@148.65,77.25 ; 148.65,78.025 R556.1@148.65,77.25 ; 148.65,78.475 R557.1@148.65,79.25 ; 148.65,80.025 R557.1@148.65,79.25 ; 148.65,80.475 C674.1@148.65,81.25 ; 148.65,82.025 C674.1@148.65,81.25 ; 148.65,82.475 R643.1@148.65,83.25 ; 148.65,84.025 R643.1@148.65,83.25 ; 148.75,91.025 R608.1@148.75,91.85 ; v1@148.75,92.675 R608.1@148.75,91.85 ; 149.475,61.25 C695.1@148.65,61.25 ; 149.475,63.25 C670.2@148.65,63.25 ; 149.475,65.25 C671.1@148.65,65.25 ; 149.475,73.25 C672.1@148.65,73.25 ; 149.475,75.25 C699.1@148.65,75.25 ; 149.475,77.25 R556.1@148.65,77.25 ; 149.475,79.25 R557.1@148.65,79.25 ; 149.475,81.25 C674.1@148.65,81.25 ; 149.475,83.25 R643.1@148.65,83.25 ; 149.525,91.85 R608.1@148.75,91.85 ; 149.975,91.85 R606.1@150.75,91.85 ; 150.75,91.025 R606.1@150.75,91.85 ; v1@150.75,92.675 R606.1@150.75,91.85 ; 151.525,91.85 R606.1@150.75,91.85 ; 151.975,91.85 R554.1@152.75,91.85 ; 152.75,91.025 R554.1@152.75,91.85 ; v1@152.75,92.675 R554.1@152.75,91.85 ; 153.525,91.85 R554.1@152.75,91.85 ; 153.975,91.85 R558.1@154.75,91.85 ; 154.75,91.025 R558.1@154.75,91.85 ; v1@154.75,92.675 R558.1@154.75,91.85 ; 155.525,91.85 R558.1@154.75,91.85 ; 156.025,74.75 R638.1@156.85,74.75 ; 156.025,76.75 C673.1@156.85,76.75 157.675,76.75 ; 156.025,78.75 R600.1@156.85,78.75 157.675,78.75 ; 156.025,80.75 R602.1@156.85,80.75 157.675,80.75 ; 156.025,82.75 R640.1@156.85,82.75 157.675,82.75 ; 156.025,84.75 R644.1@156.85,84.75 157.675,84.75 ; v1@156.85,75.525 R638.1@156.85,74.75 ; 157.675,74.75 R638.1@156.85,74.75 ; 166.75,66.025 Q541.4@167.35,66.025 ; 167.25,72.275 Q540.4@167.85,72.275 167.85,71.375 ; 167.35,65.125 Q541.4@167.35,66.025 ; 167.35,66.925 Q541.4@167.35,66.025 ; 168.65,63.075 Q541.1@168.65,63.975 ; 168.65,64.875 Q541.1@168.65,63.975 ; v1@169.15,69.325 Q540.1@169.15,70.225 ; 169.15,71.125 Q540.1@169.15,70.225 ; 169.25,63.975 Q541.1@168.65,63.975 ; 169.75,70.225 Q540.1@169.15,70.225 ; C926.2@175.35,37 v1(176.375,37) ; v1(175.35,45.75) R948.1@175.35,46.75 R954.2@175.35,48.75 175.35,50.475 v1(176.375,51.5) C928.2@177.4,51.5 ; R949.1@179.1,44.75 v1(180.125,44.75) 180.125,46.5 180.375,46.75 R955.2@181.15,46.75 181.15,47.275 181.375,47.5 183.625,47.5 ; C927.2@182.85,37 183.625,37 183.875,37.25 v1(183.875,38.25) v1(183.875,41.125) v1(183.875,46.75) 183.875,47.25 ; v1(183.875,51.75) 183.875,47.75 ; C746.2@189.85,40 v1(190.875,40) ; v1(189.85,48.75) R848.1@189.85,49.75 R854.2@189.85,51.75 189.85,52.35 191.75,54.25 192.65,54.25 192.9,54.5 C748.2@192.9,55.25 v1(191.875,55.25) CN515.1@190,55.25 ; v1(192.75,48.75) 192.75,48 193,47.75 R849.1@193.6,47.75 194.375,47.75 194.625,48 194.625,49.5 194.875,49.75 R855.2@195.65,49.75 195.65,50.4 195.75,50.5 v1(198.25,50.5) v1(198.25,41.125) 198.25,40.225 198.025,40 C747.2@197.35,40 ; v1(200.75,57) 204,60.25 v1(204,61.875) 204,62.875 ; CN512.1@203.75,55.5 v1(205.625,55.5) C738.2@206.65,55.5 206.65,54.5 204.35,52.2 R754.2@204.35,51.75 R748.1@204.35,49.75 v1(204.35,48.75) ; C929.2@204,64.15 204,63.375 ; C736.2@204.35,40 v1(205.375,40) ; v1(206.85,63.125) 204.25,63.125 ; v1(207.25,48.75) 207.25,48 207.5,47.75 R749.1@208.1,47.75 208.875,47.75 209.125,48 209.125,49.5 209.375,49.75 R755.2@210.15,49.75 210.15,50.25 210.4,50.5 v1(212.75,50.5) v1(212.75,41.25) 212.75,40.25 212.5,40 C737.2@211.85,40 ; CN912.1@218,56.5 C918.2@220.9,56.5 220.9,55.525 218.85,53.475 R934.2@218.85,52.75 R928.1@218.85,50.75 v1(218.85,49.75) ; C916.2@218.85,41 v1(219.875,41) ; R929.1@222.6,48.75 v1(223.625,48.75) 223.625,50.5 223.875,50.75 R935.2@224.65,50.75 224.65,51.4 225.375,52.125 v1(227.25,52.125) ; C917.2@226.35,41 227,41 227.25,41.25 v1(227.25,42.25) v1(227.25,52.125) ; v1(226.625,56.5) 226.625,52.75 v1(227.25,52.125) ; v1(228.5,56.5) 229.125,57.125 229.125,60.25 v1(232.25,63.375) C919.2@232.25,65.65 ; CN505.1@232,56.5 v1(233.875,56.5) C728.2@234.9,56.5 234.9,55.5 233.35,53.95 R834.2@233.35,52.75 R828.1@233.35,50.75 v1(233.35,49.75) ; C726.2@233.35,41 v1(234.375,41) ; R829.1@237.1,48.75 v1(238.125,48.75) 238.125,50.5 238.375,50.75 R835.2@239.15,50.75 239.15,51.4 239.625,51.875 v1(240.65,51.875) v1(240.65,57.375) ; C727.2@240.85,41 v1(240.85,42.125) ; CN502.1@247,56.5 v1(248.875,56.5) C718.2@249.9,56.5 249.9,55.5 248.35,53.95 R734.2@248.35,52.75 R728.1@248.35,50.75 v1(248.35,49.75) ; C716.2@248.35,41 v1(249.375,41) ; R729.1@252.1,48.75 v1(253.125,48.75) 253.125,50.5 253.375,50.75 R735.2@254.15,50.75 254.15,51.4 254.5,51.75 v1(256.875,51.75) ; C717.2@255.85,41 256.625,41 256.875,41.25 v1(256.875,42.25) v1(256.875,51.75) ; v1(256.875,58.125) v1(256.875,51.75) ; 183.625,47.5 183.875,47.25 ; 183.625,47.5 183.875,47.75 ; 183.875,47.25 183.875,47.75 ; 204,62.875 204,63.375 ; 204,62.875 204.25,63.125 ; 204,63.375 204.25,63.125
  BOTTOM w0.5: v1(156.85,75.75) C673.1@156.85,76.75 R600.1@156.85,78.75 v1(156.85,79.75) R602.1@156.85,80.75 R640.1@156.85,82.75 R644.1@156.85,84.75 v2(156.85,85.875) ; 159.206,36.956 CN958.1@160.125,37.875 ; 159.206,38.794 CN958.1@160.125,37.875 ; 161.044,36.956 CN958.1@160.125,37.875 ; 161.044,38.794 CN958.1@160.125,37.875
  other v1: 125,35 148.5,35.025 149.5,35.5 144.75,36.875 124,37 143.75,37.5 169.875,47 132.25,56.125 188.65,62.375 198.15,62.375 156.85,62.5 168.65,62.5 178.65,62.5 138.5,66.5 144.5,66.5 146,66.5 167.35,67.25 177.35,67.25 187.35,67.25 196.85,67.25 137,68 138.5,68 169.15,69.125 178.65,69.125 188.65,69.125 198.15,69.125 137,71 138.5,71 140,71 141.5,71 143,71 144.5,71 146,71 137,74 138.5,74 140,74 141.5,74 143,74 137,75.5 138.5,75.5 140,75.5 141.5,75.5 143,75.5 146,75.5 147.5,75.5 104.392,75.722 106.233,75.722 137,77 138.5,77 140,77 141.5,77 143,77 146,77 147.5,77 142.75,92.875 144.75,92.875 146.75,92.875 148.75,92.875 150.75,92.875 152.75,92.875 154.75,92.875 108.625,97.75 119.5,98 108.625,99 119.5,100 121.4,101
DIAG0-1: CN3.6 IC600.27 R515.2 | length 181
  TOP w0.25: v1(136,82) 136,84.125 137.75,85.875 IC600.27@137.75,86.8 137.75,87.625 138.125,88 138.45,88 139.5,89.05 139.5,93.375 v1(139.25,93.625)
  BOTTOM w0.25: R515.2@136,80.85 v1(136,82) ; v1(139.25,93.625) 141.625,93.625 142.125,94.125 155.25,94.125 157,92.375 181.375,92.375 182.75,93.75 210.75,93.75 218.125,86.375 218.125,70.375 218.375,70.125 234,70.125 243.25,60.875 243.25,25 CN3.6@244.75,23.5
DIAG0-2: CN103.6 IC600.130 R525.1 | length 51.2
  TOP w0.25: v1(145.75,67.65) 147.1,67.65 150.125,64.625 150.125,62.5 149.75,62.125 IC600.130@149.75,61.2 149.75,48 v1(152.625,45.125)
  BOTTOM w0.25: v1(145.75,67.65) R525.1@146.75,67.65 ; v1(152.625,45.125) 156,41.75 156,25.25 CN103.6@157.75,23.5
DIAG0-3: CN203.6 IC600.103 R535.1 | length 45.8
  TOP w0.25: v1(129.75,37.875) 129.75,43.875 130.75,44.875 130.75,49.875 135.25,54.375 135.25,57.875 135,58.125 v1(135,58.5) ; IC600.103@136.25,61.2 v1(136.25,62.5)
  BOTTOM w0.25: CN203.6@124.75,23.5 128.5,27.25 128.5,36.625 v1(129.75,37.875) ; v1(135,58.5) 135.35,58.85 R535.1@136.25,58.85 v1(136.25,62.5)
DIAG0-4: CN303.6 IC600.141 R545.2 | length 172.3
  TOP w0.25: CN303.6@37.75,23.5 37.75,29.5 38,29.75 126.25,29.75 126.5,30 v1(126.5,48) ; v1(151.5,68.25) 151.5,67.625 151.875,67.25 IC600.141@152.8,67.25 156.75,67.25 157.625,66.375 159,66.375 159.25,66.125 159.25,63 159.125,62.875 159.125,52.125 v1(158.625,51.625)
  BOTTOM w0.25: v1(126.5,48) 127.25,48.75 132.625,48.75 134,50.125 157.125,50.125 v1(158.625,51.625) ; R545.2@150.35,69.25 151.25,69.25 151.5,69 v1(151.5,68.25)
EN_1R2V: D620.2 IC620.1 J829.2 R632.1 | length 12.8
  TOP w0.25: R632.1@137.5,45.15 138.25,45.15 138.5,44.9 ; v1(138.487,40.5) 138.487,44.388 ; IC620.1@139.55,44.65 138.75,44.65 ; 138.487,44.388 138.75,44.65 ; 138.487,44.388 138.487,44.887 138.5,44.9 ; 138.5,44.9 138.535,44.865 138.75,44.65
  BOTTOM w0.25: J829.2@135.5,39.375 135.5,40.25 ; D620.2@135.5,41.65 135.5,40.75 ; v1(138.487,40.5) 135.75,40.5 ; 135.5,40.25 135.75,40.5 ; 135.5,40.25 135.5,40.75 ; 135.5,40.75 135.75,40.5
